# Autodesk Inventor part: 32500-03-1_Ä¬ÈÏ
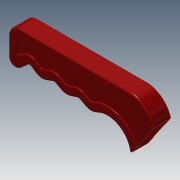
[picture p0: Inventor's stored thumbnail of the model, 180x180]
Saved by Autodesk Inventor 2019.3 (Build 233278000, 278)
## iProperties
Created: 2010-06
Part Number: 32500-03-1_Ä¬ÈÏ
Material: Ogólny
Document SubType Name: Modeling
Designer: CADENGINEERING4
Density: 1 g/cm^3
Appearance: Czerwona
Author: CADENGINEERING4
Revision Number: ÈÎºÎ
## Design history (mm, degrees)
feature "NONE"
node "Bryła1"
